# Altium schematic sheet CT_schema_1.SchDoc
size 554 x 416 mm
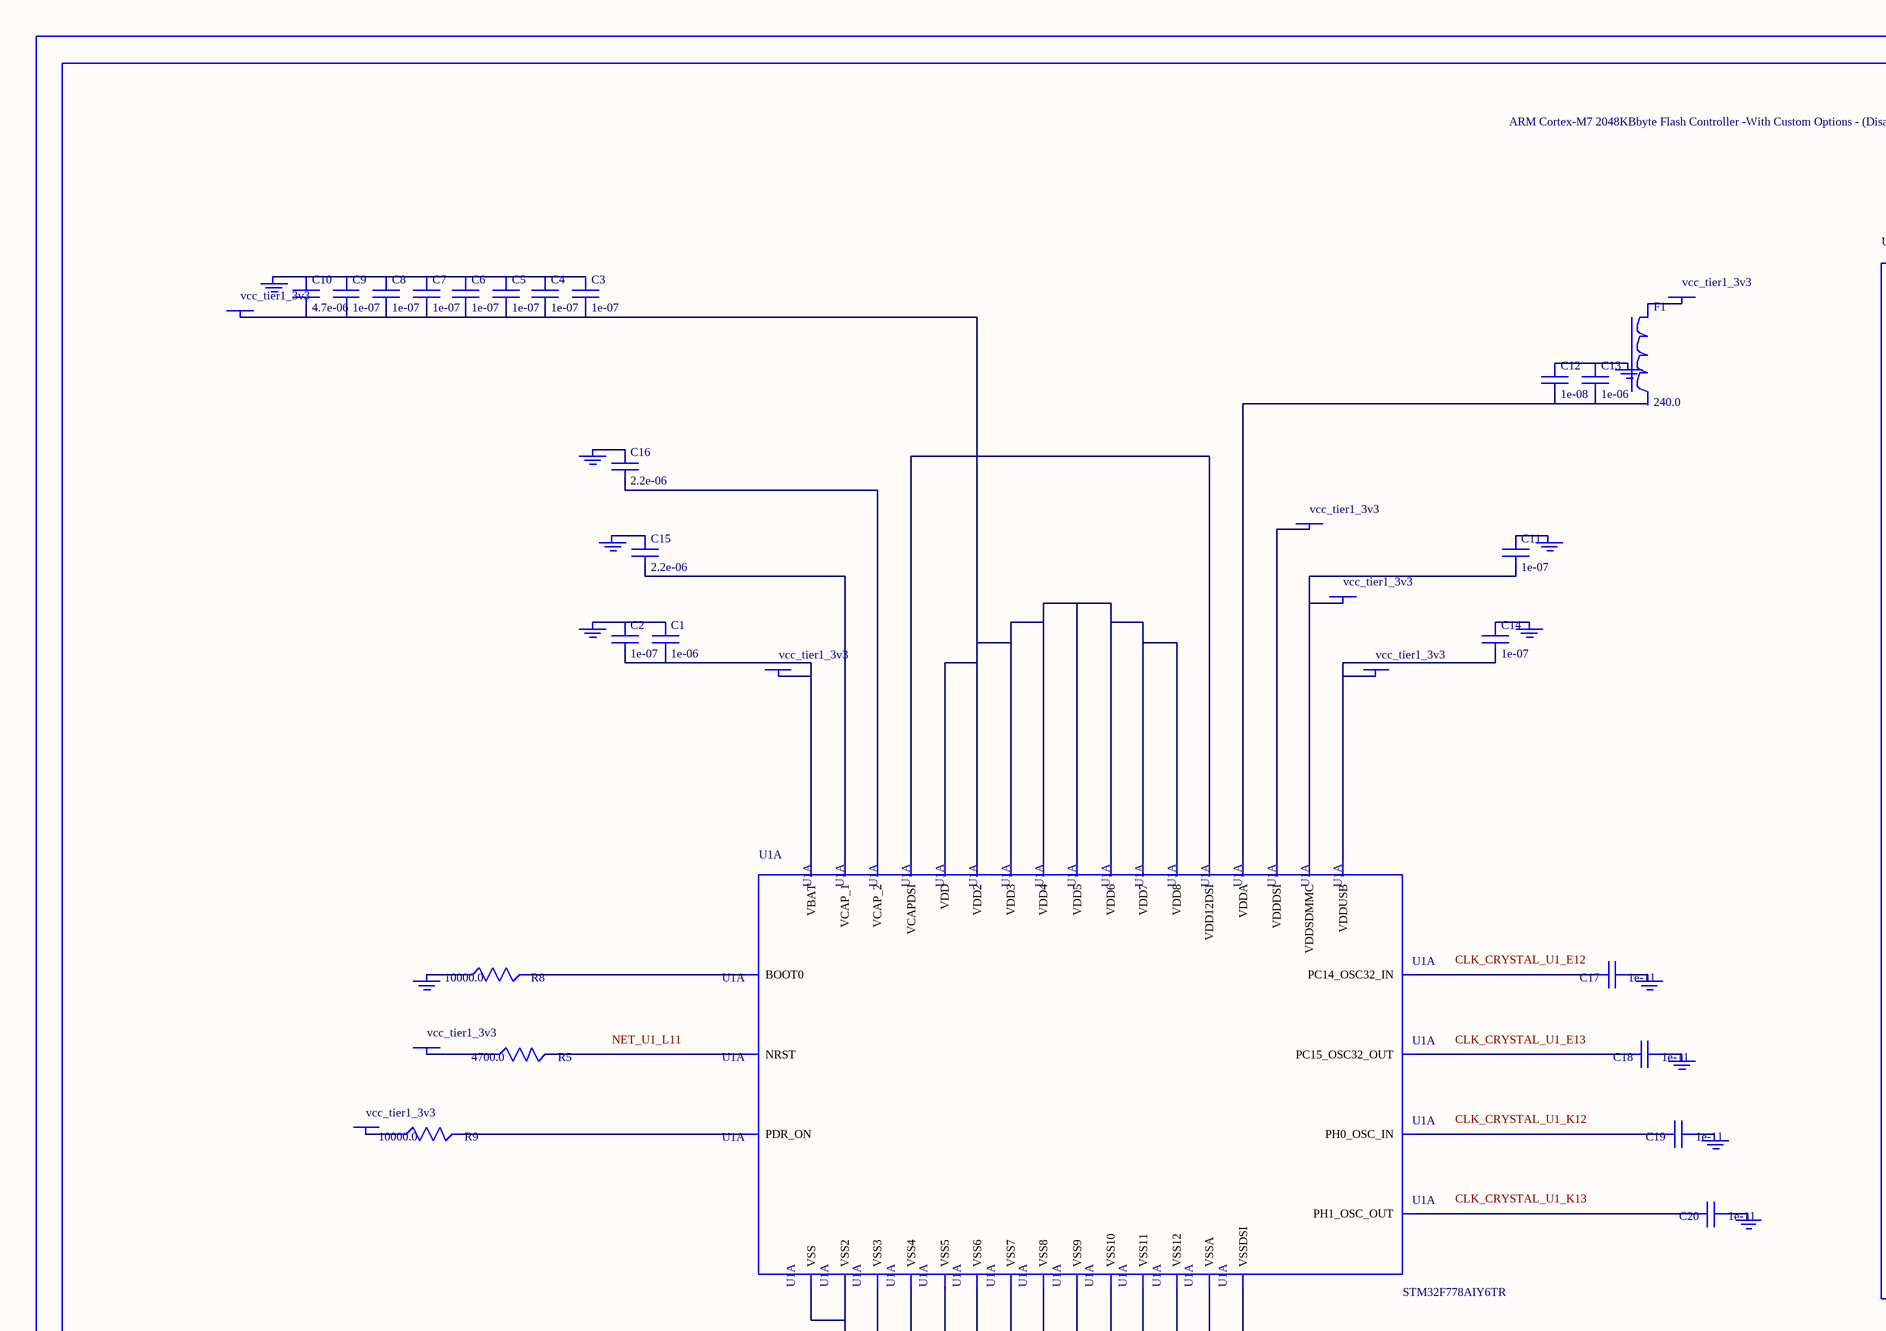
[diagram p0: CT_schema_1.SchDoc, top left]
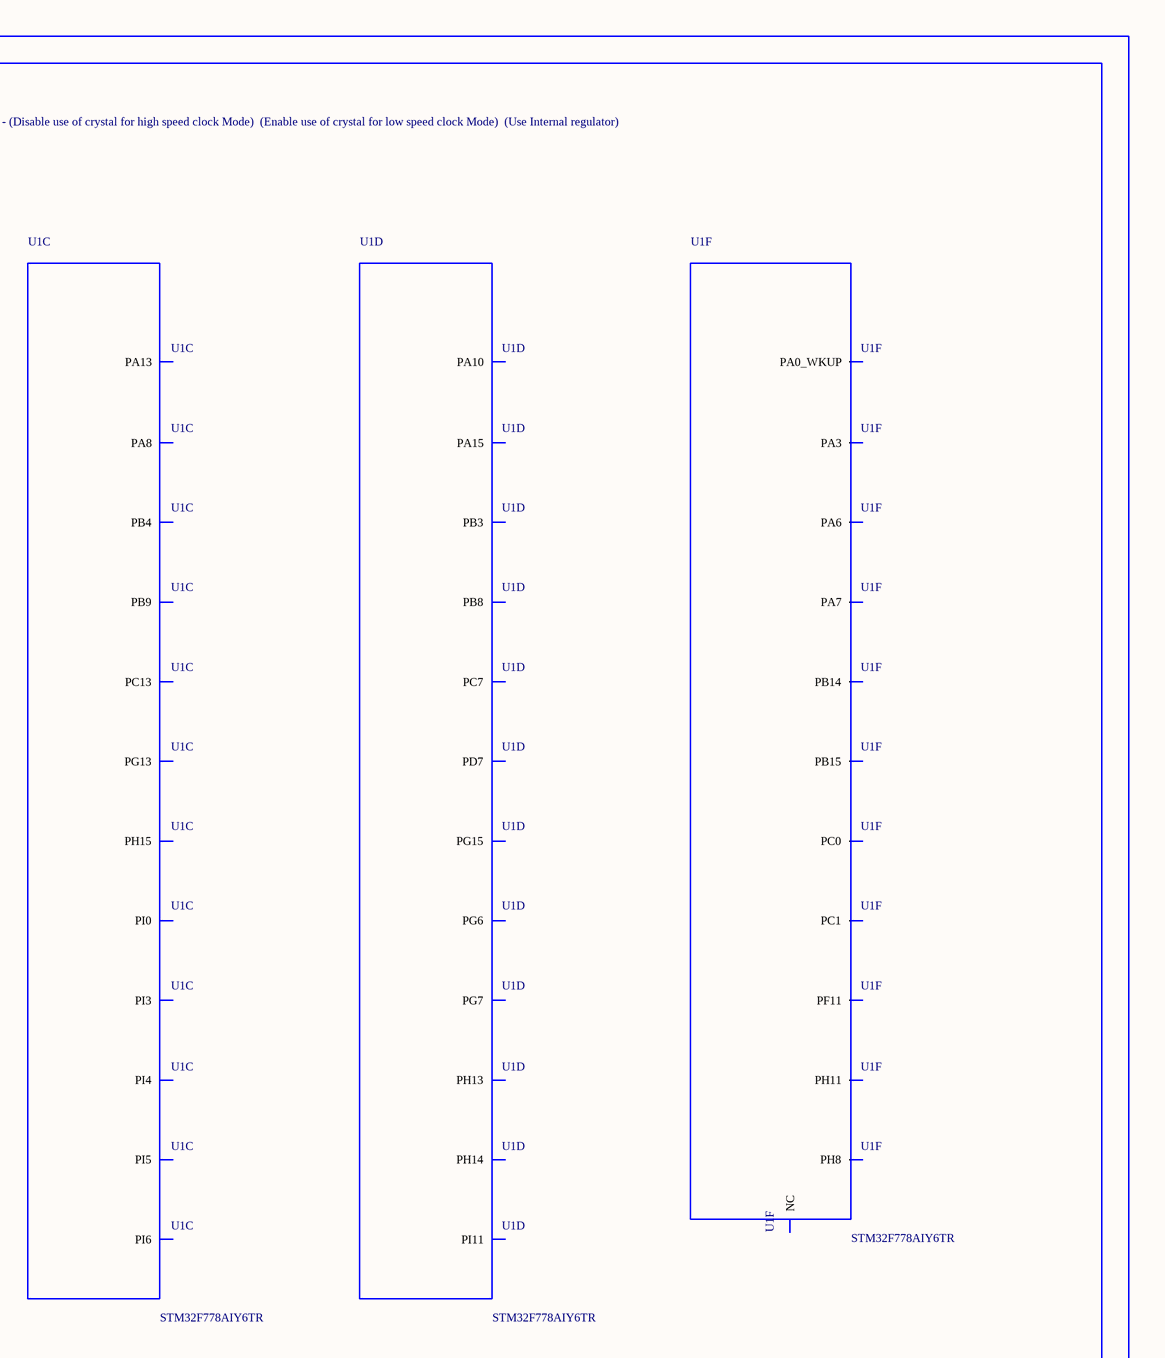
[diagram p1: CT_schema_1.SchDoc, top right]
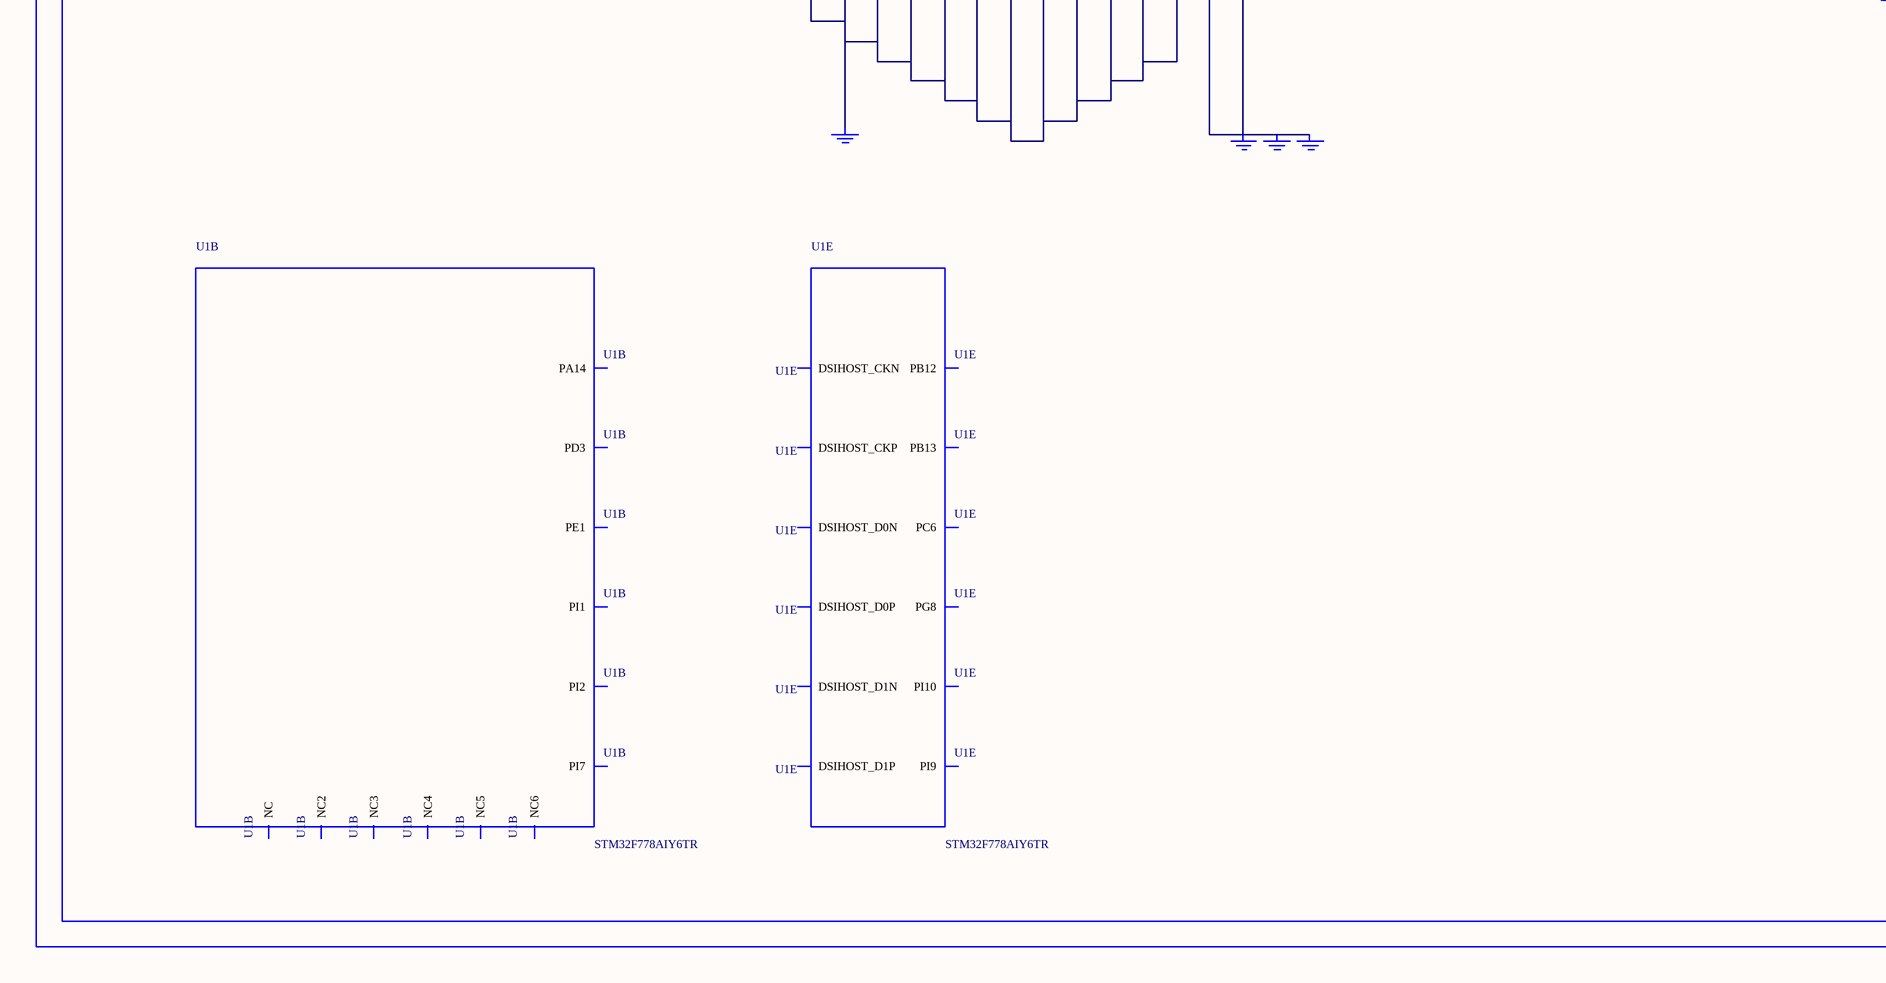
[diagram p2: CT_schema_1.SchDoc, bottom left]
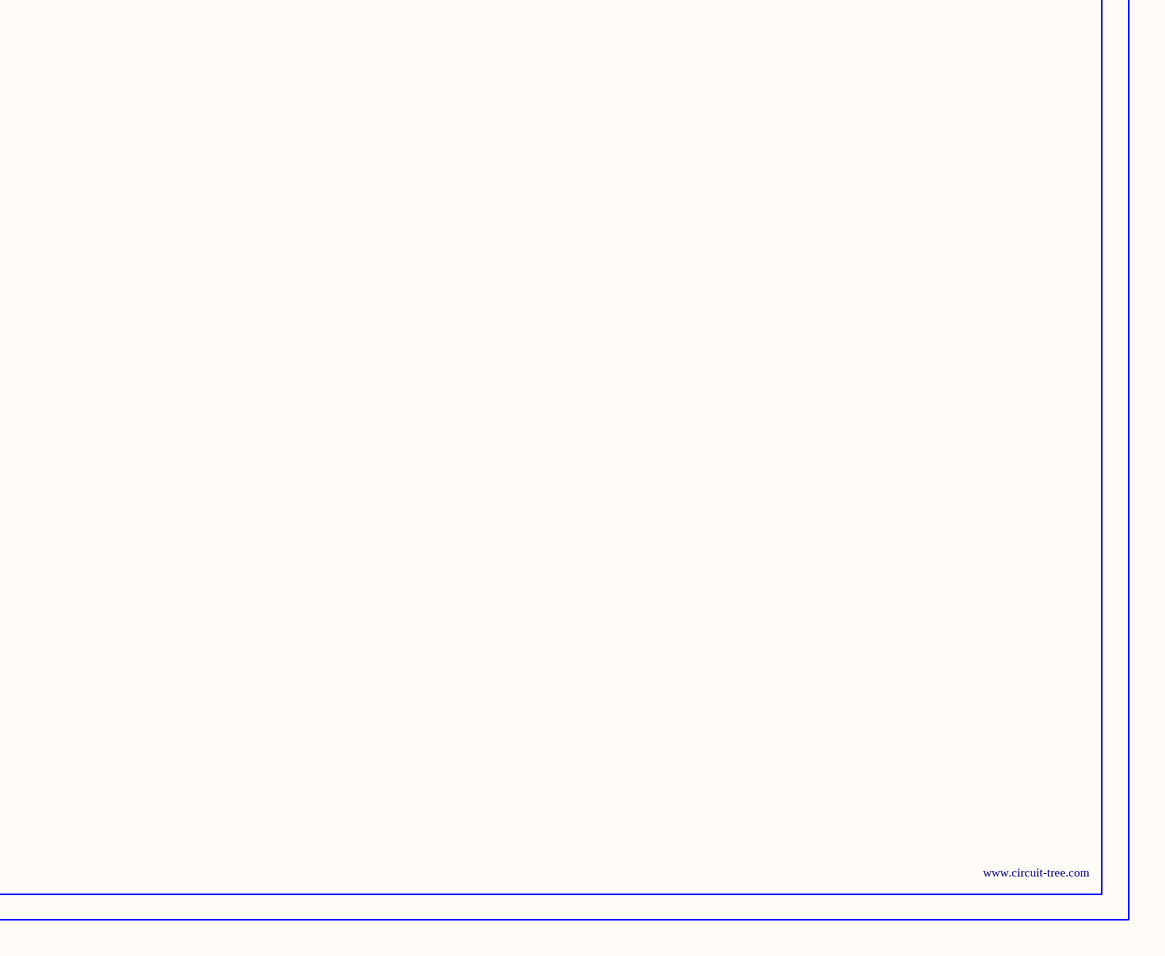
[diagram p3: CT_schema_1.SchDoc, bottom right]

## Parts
BORDER0  (no value)
C1  1e-06  [C0603]
C2  1e-07  [C0603]
C3  1e-07  [C0603]
C4  1e-07  [C0603]
C5  1e-07  [C0603]
C6  1e-07  [C0603]
C7  1e-07  [C0603]
C8  1e-07  [C0603]
C9  1e-07  [C0603]
C10  4.7e-06  [C0603]
C11  1e-07  [C0603]
C12  1e-08  [C0603]
C13  1e-06  [C0603]
C14  1e-07  [C0603]
C15  2.2e-06  [C0603]
C16  2.2e-06  [C0603]
C17  1e-11  [C0402]
C18  1e-11  [C0402]
C19  1e-11  [C0402]
C20  1e-11  [C0402]
F1  240.0  [L0603]
GND_INSTANCE_0_0  (no value)
GND_INSTANCE_0_1  (no value)
GND_INSTANCE_0_2  (no value)
GND_INSTANCE_0_3  (no value)
GND_INSTANCE_0_4  (no value)
GND_INSTANCE_0_5  (no value)
GND_INSTANCE_0_6  (no value)
GND_INSTANCE_0_7  (no value)
GND_INSTANCE_0_8  (no value)
GND_INSTANCE_0_9  (no value)
GND_INSTANCE_0_10  (no value)
GND_INSTANCE_0_11  (no value)
GND_INSTANCE_0_12  (no value)
GND_INSTANCE_0_13  (no value)
GND_INSTANCE_0_14  (no value)
GND_INSTANCE_0_15  (no value)
POWER_INSTANCE_0_0  vcc_tier1_3v3
POWER_INSTANCE_0_1  vcc_tier1_3v3
POWER_INSTANCE_0_2  vcc_tier1_3v3
POWER_INSTANCE_0_3  vcc_tier1_3v3
POWER_INSTANCE_0_4  vcc_tier1_3v3
POWER_INSTANCE_0_5  vcc_tier1_3v3
POWER_INSTANCE_0_6  vcc_tier1_3v3
POWER_INSTANCE_0_7  vcc_tier1_3v3
R5  4700.0  [R0603]
R8  10000.0  [R0603]
R9  10000.0  [R0603]
U1  STM32F778AIY6TR  [WLCSP180]  (parts A,B,C,D,E,F of 15)

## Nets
NetC1_1: C1.1 C2.1 GND_INSTANCE_0_0.0(GND)
NetC1_2: C1.2 C2.2 POWER_INSTANCE_0_0.0(PWR) U1.C13(VBAT)
NetC3_1: C3.1 C4.1 C5.1 C6.1 C7.1 C8.1 C9.1 C10.1 GND_INSTANCE_0_2.0(GND)
NetC3_2: C3.2 C4.2 C5.2 C6.2 C7.2 C8.2 C9.2 C10.2 POWER_INSTANCE_0_2.0(PWR) U1.B2(VDD2) U1.B8(VDD3) U1.B11(VDD) U1.F12(VDD4) U1.J12(VDD5) U1.K9(VDD6) U1.M8(VDD7) U1.P4(VDD8)
NetC11_1: C11.1 GND_INSTANCE_0_4.0(GND)
NetC11_2: C11.2 POWER_INSTANCE_0_3.0(PWR) U1.A6(VDDSDMMC)
NetC12_1: C12.1 C13.1 GND_INSTANCE_0_1.0(GND)
NetC12_2: C12.2 C13.2 U1.M12(VDDA)
NetC14_1: C14.1 GND_INSTANCE_0_5.0(GND)
NetC14_2: C14.2 POWER_INSTANCE_0_5.0(PWR) U1.F2(VDDUSB)
NetC15_1: C15.1 GND_INSTANCE_0_6.0(GND)
NetC15_2: C15.2 U1.P5(VCAP_1)
NetC16_1: C16.1 GND_INSTANCE_0_7.0(GND)
NetC16_2: C16.2 U1.C1(VCAP_2)
NetC17_1: C17.1 GND_INSTANCE_0_8.0(GND)
NetC17_2: C17.2 U1.E12(PC14_OSC32_IN)
NetC18_1: C18.1 GND_INSTANCE_0_9.0(GND)
NetC18_2: C18.2 U1.E13(PC15_OSC32_OUT)
NetC19_1: C19.1 GND_INSTANCE_0_10.0(GND)
NetC19_2: C19.2 U1.K12(PH0_OSC_IN)
NetC20_1: C20.1 GND_INSTANCE_0_11.0(GND)
NetC20_2: C20.2 U1.K13(PH1_OSC_OUT)
NetF1_1: F1.1 POWER_INSTANCE_0_1.0(PWR)
NetGND_INSTANCE_0_3_0: GND_INSTANCE_0_3.0(GND) R8.1
NetGND_INSTANCE_0_12_0: GND_INSTANCE_0_12.0(GND) GND_INSTANCE_0_13.0(GND) GND_INSTANCE_0_14.0(GND) U1.H5(VSSDSI) U1.M11(VSSA)
NetGND_INSTANCE_0_15_0: GND_INSTANCE_0_15.0(GND) U1.A8(VSS2) U1.A11(VSS) U1.B6(VSS3) U1.C2(VSS4) U1.F1(VSS5) U1.F13(VSS6) U1.J9(VSS8) U1.J13(VSS7) U1.M1(VSS9) U1.N4(VSS10) U1.N5(VSS11) U1.P9(VSS12)
NetPOWER_INSTANCE_0_4_0: POWER_INSTANCE_0_4.0(PWR) R9.1
NetPOWER_INSTANCE_0_6_0: POWER_INSTANCE_0_6.0(PWR) U1.K1(VDDDSI)
NetPOWER_INSTANCE_0_7_0: POWER_INSTANCE_0_7.0(PWR) R5.1
NetR5_2: R5.2 U1.L11(NRST)
NetR8_2: R8.2 U1.A10(BOOT0)
NetR9_2: R9.2 U1.C10(PDR_ON)
NetU1_H6: U1.H6(VCAPDSI) U1.J3(VDD12DSI)

Not connected (* = marked no-connect by the designer): F1 2; U1 A1(NC) A2(NC4) A3(PA14) A12(NC2) A13(NC3) B1(NC5) B3(PI1) B5(PD3) B10(PE1) B12(PI7) B13(NC6) C3(PI2) C7(PG13) C11(PI6) D2(PA13) D3(PI3) D8(PB4) D9(PB9) D10(PI4) D11(PI5) D13(PC13) E2(PA8) E4(PI0) E5(PH15) E7(PD7) E8(PB3) E9(PB8) F3(PC7) F5(PA10) F6(PH13) F7(PH14) F8(PA15) F9(PG15) F11(PI11) G3(PG6) G4(PG7) G5(PG8) G6(PC6) G10(PI9) H1(DSIHOST_D1P) H2(DSIHOST_D1N) H3(DSIHOST_CKN) H4(DSIHOST_CKP) H8(PB12) H10(PI10) J1(DSIHOST_D0P) J2(DSIHOST_D0N) J5(PB13) L12(PC0) L13(PC1) M4(PH11) M5(PH8) M9(PA7) M10(PA3) M13(PA0_WKUP) N1(NC) N2(PB15) N3(PB14) N9(PF11) N10(PA6)

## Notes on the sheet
- Labels drawn without touching a wire or pin: CLK_CRYSTAL_U1_E12, CLK_CRYSTAL_U1_E13, CLK_CRYSTAL_U1_K12, CLK_CRYSTAL_U1_K13, NET_U1_L11

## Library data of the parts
BORDER0 = BORDER_PAGE0
C1 C13 = C0603C105K3RACTU
C2-C9 C11 C14 = 06035C104K4Z2A
C10 = GRM188R6YA475KE15D
C12 = 06035C103K4Z2A
C15 C16 = C0603C225K8RACTU
C17-C20 = C0402C100K3GACTU
F1 = Z0603C241ASMST
GND_INSTANCE_0_0-GND_INSTANCE_0_15 = GND
POWER_INSTANCE_0_0-POWER_INSTANCE_0_7 = PWR
R5 = RC0603JR-074K7L
R8 R9 = RC0603JR-0710KL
